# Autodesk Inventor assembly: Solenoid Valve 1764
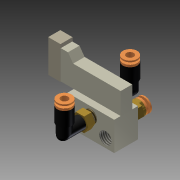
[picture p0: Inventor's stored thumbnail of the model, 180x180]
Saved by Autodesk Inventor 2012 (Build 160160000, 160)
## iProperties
Created: 2010-02
Part Number: Solenoid Valve 1764
Document SubType Name: Assembly
Designer: jgehrig
Author: jgehrig
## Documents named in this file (5)
- R:\CAD Archives\Pneumatics_1764\Soloniod_1764\Solenoid_Valve_1764.iam
- R:\CAD Archives\Pneumatics_1764\Soloniod_1764\Pneumatic_Screw_1764\Pneumatic_Screw_1764.iam
- R:\CAD Archives\Pneumatics_1764\Soloniod_1764\Pneumatics_Bend_Piece_1764\Pneumatic_Bend_Piece_1764.iam
- R:\CAD Archives\Pneumatics_1764\Soloniod_1764\Solenoid_Part_1764.ipt
- R:\CAD Archives\Pneumatics_1764\Soloniod_1764\Solenoid_Base_1764.ipt
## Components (5 placed, 4 different names)
1. Solenoid_Base_1764:1 — Flush:1, Mate:1, Flush:2, Insert:3, Insert:4, Insert:5
2. Solenoid_Part_1764:1 — Flush:1, Mate:1, Flush:2, Angle:4, Angle:5
3. Pneumatic_Screw_1764:1 [sub-assembly] — Insert:3
4. Pneumatic_Bend_Piece_1764:1 [sub-assembly] — Insert:5, Angle:4
5. Pneumatic_Bend_Piece_1764:2 [sub-assembly] — Insert:4, Angle:5
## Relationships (8: Insert 3, Flush 2, Angle 2, Mate 1)
- Flush:1: Solenoid_Base_1764:1 ↔ Solenoid_Part_1764:1
- Mate:1: Solenoid_Base_1764:1 ↔ Solenoid_Part_1764:1
- Flush:2: Solenoid_Base_1764:1 ↔ Solenoid_Part_1764:1
- Insert:3: Solenoid_Base_1764:1 ↔ Pneumatic_Screw_1764:1
- Insert:4: Solenoid_Base_1764:1 ↔ Pneumatic_Bend_Piece_1764:2
- Insert:5: Solenoid_Base_1764:1 ↔ Pneumatic_Bend_Piece_1764:1
- Angle:4: Solenoid_Part_1764:1 ↔ Pneumatic_Bend_Piece_1764:1
- Angle:5: Solenoid_Part_1764:1 ↔ Pneumatic_Bend_Piece_1764:2
